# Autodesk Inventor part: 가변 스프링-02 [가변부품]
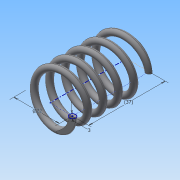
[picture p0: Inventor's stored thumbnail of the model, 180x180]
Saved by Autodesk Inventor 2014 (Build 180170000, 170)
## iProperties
Created: 2015-09
Part Number: 가변 스프링-02 [가변부품]
Material: 강철, 탄소
Document SubType Name: Modeling
Designer: study
Density: 7.87 g/cm^3
Appearance: 반연마
Mass: 18.8856 g
Surface Area: 32.5491 cm^2
Volume: 2.3997 cm^3
Author: study
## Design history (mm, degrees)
sketch "스케치1"
  geometry: L1 (0, 0)-(11, 0); L2 (11, 0)-(11, 36.411); L3 (11, 36.411)-(0, 36.411); L4 (0, 36.411)-(0, 0); C1 r 1.5 at (11, 0)
  constraints: 8 end point, 2 parallel, 1 centre point, 1 coincident, 1 horizontal, 1 perpendicular
  dimensions: "d0" = 36.4112 distance of L1.end L2.end (derived); "d1" = 22 diameter of L2 L4; "d2" = 3 diameter of C1
feature "코일1" sketch "스케치1" pitch "d3" = 10; turns "d5" = 5; dims "d4" = 36.4112 (= d0), "d6" = 0, angle "d7" = 90 deg, angle "d8" = 90 deg, "d9" = 0, "d10" = 0
node "작업 평면1"
sketch "스케치2"
  geometry: L1 (-12.5, 0)-(-9.5, 0) reference; 1 further point
  constraints: 1 horizontal alignment
extrude "돌출1" cut sketch "스케치2" stored distance "d12" = 10; taper "d13" = 0 deg
node "작업 평면2"
sketch "스케치3"
  geometry: L1 (-9.5, 0)-(-12.5, 0) reference; 1 further point
  constraints: 1 horizontal alignment
extrude "돌출2" cut sketch "스케치3" stored distance "d15" = 10; taper "d16" = 0 deg
node "솔리드1"
node "절단 모서리 투영1"
node "절단 모서리 투영2"
other parameters: "d11" = 0, "d14" = 36.4112 (= d0)
